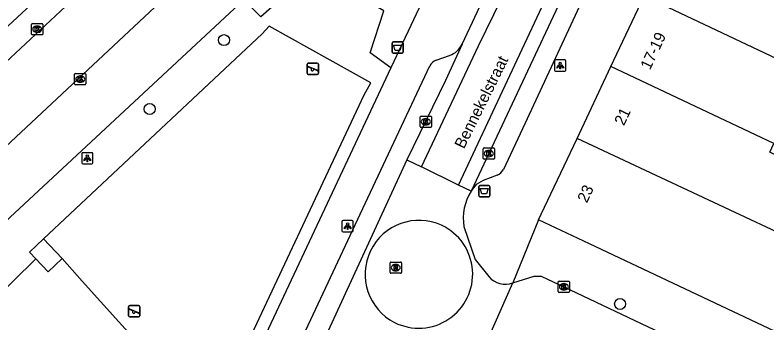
# Model space of a CAD drawing. Extents: x 159822 to 160765, y 380693 to 381634.
# Drawn here: x 160159 to 160225.7, y 381490.4 to 381517.7 of the extents above; entities that cross this region are included whole.
import ezdxf

# ---------------------------------------------------------------- set-up
doc = ezdxf.new("R2010")
doc.units = 0
for name, color, linetype in [('IMGEO_Afvalbak', 7, 'Continuous'), ('IMGEO_Boom', 7, 'Continuous'), ('IMGEO_Groenvoorziening', 7, 'Continuous'), ('IMGEO_Hek', 7, 'Continuous'), ('IMGEO_Kolk', 7, 'Continuous'), ('IMGEO_Lichtpunt', 7, 'Continuous'), ('IMGEO_Openbare_ruimte_label', 7, 'Continuous'), ('IMGEO_Pand', 7, 'Continuous'), ('IMGEO_Pand_nummerreeks', 7, 'Continuous'), ('IMGEO_Parkeervlak_open', 7, 'Continuous'), ('IMGEO_Rijbaan_lokaal_gesloten', 7, 'Continuous'), ('IMGEO_Rijbaan_lokaal_open', 7, 'Continuous'), ('IMGEO_Rioolput', 7, 'Continuous'), ('IMGEO_Speelvoorziening', 7, 'Continuous'), ('IMGEO_Voetpad_open', 7, 'Continuous')]:
    doc.layers.add(name, color=color, linetype=linetype)

msp = doc.modelspace()

# ---------------------------------------------------------------- linework, layer by layer
at = {"layer": 'IMGEO_Afvalbak'}
for p, q in [((160192.441, 381514.386), (160192.441, 381515.186)), ((160192.441, 381515.186), (160192.441, 381514.386)), ((160192.541, 381515.286), (160193.331, 381515.286)), ((160193.331, 381515.286), (160192.541, 381515.286)), ((160193.431, 381515.186), (160193.431, 381514.386)), ((160193.431, 381514.386), (160193.431, 381515.186)), ((160193.331, 381514.286), (160192.541, 381514.286)), ((160192.541, 381514.286), (160193.331, 381514.286)), ((160200.135, 381501.653), (160200.135, 381502.453)), ((160200.135, 381502.453), (160200.135, 381501.653)), ((160200.235, 381502.553), (160201.025, 381502.553)), ((160201.025, 381502.553), (160200.235, 381502.553)), ((160201.125, 381502.453), (160201.125, 381501.653)), ((160201.125, 381501.653), (160201.125, 381502.453)), ((160201.025, 381501.553), (160200.235, 381501.553)), ((160200.235, 381501.553), (160201.025, 381501.553))]:
    msp.add_line(p, q, dxfattribs=at)
for points in [[(160192.584, 381515), (160193.288, 381515), (160193.139, 381514.53), (160192.733, 381514.53), (160192.584, 381515)], [(160200.278, 381502.267), (160200.982, 381502.267), (160200.833, 381501.797), (160200.427, 381501.797), (160200.278, 381502.267)]]:
    msp.add_lwpolyline(points, dxfattribs=at)
for centre, start, end in [((160192.541, 381515.186), 90, 180), ((160192.541, 381515.186), 90, 180), ((160193.331, 381515.186), 0, 90), ((160193.331, 381515.186), 360, 90), ((160192.541, 381514.386), 180, 270), ((160192.541, 381514.386), 180, 270), ((160193.331, 381514.386), 270, 0), ((160193.331, 381514.386), 270, 0), ((160200.235, 381502.453), 90, 180), ((160200.235, 381502.453), 90, 180), ((160201.025, 381502.453), 0, 90), ((160201.025, 381502.453), 360, 90), ((160200.235, 381501.653), 180, 270), ((160200.235, 381501.653), 180, 270), ((160201.025, 381501.653), 270, 0), ((160201.025, 381501.653), 270, 0)]:
    msp.add_arc(centre, 0.1, start, end, dxfattribs=at)
at = {"layer": 'IMGEO_Boom'}
for centre in [(160177.513, 381515.444), (160170.915, 381509.333), (160212.692, 381492.04)]:
    msp.add_circle(centre, 0.489, dxfattribs=at)
at = {"layer": 'IMGEO_Groenvoorziening'}
for points in [[(160192.336, 381512.972), (160190.484, 381514.325), (160191.703, 381518.048), (160185.933, 381521.407), (160184.737, 381521.011), (160180.794, 381517.52), (160179.28, 381519.057)], [(160178.058, 381485.251), (160178.153, 381485.454), (160189.969, 381510.58), (160190.545, 381511.66), (160181.534, 381516.692), (160180.912, 381516.008), (160161.494, 381497.825)], [(160161.494, 381497.825), (160160.238, 381496.64), (160160.793, 381496.052)], [(160163.145, 381496.074), (160161.494, 381497.825)], [(160156.718, 381492.041), (160160.793, 381496.052)], [(160160.793, 381496.052), (160161.889, 381494.889), (160163.145, 381496.074)], [(160163.145, 381496.074), (160164.913, 381494.072), (160171.689, 381486.562)]]:
    msp.add_lwpolyline(points, dxfattribs=at)
at = {"layer": 'IMGEO_Hek'}
for points in [[(160190.545, 381511.66), (160181.534, 381516.692)], [(160161.494, 381497.825), (160180.912, 381516.008)], [(160178.058, 381485.251), (160178.153, 381485.454), (160189.969, 381510.58), (160190.545, 381511.66)], [(160164.913, 381494.072), (160171.689, 381486.562)]]:
    msp.add_lwpolyline(points, dxfattribs=at)
at = {"layer": 'IMGEO_Kolk'}
for p, q in [((160160.429, 381515.981), (160160.429, 381516.833)), ((160160.504, 381516.907), (160161.356, 381516.907)), ((160160.917, 381516.687), (160160.942, 381516.687)), ((160161.43, 381516.833), (160161.43, 381515.981)), ((160161.356, 381515.907), (160160.504, 381515.907)), ((160160.94, 381516.127), (160160.915, 381516.127)), ((160164.252, 381511.559), (160164.252, 381512.411)), ((160164.327, 381512.485), (160165.179, 381512.485)), ((160164.74, 381512.265), (160164.765, 381512.265)), ((160165.253, 381512.411), (160165.253, 381511.559)), ((160164.763, 381511.705), (160164.738, 381511.705)), ((160165.179, 381511.485), (160164.327, 381511.485)), ((160194.942, 381507.776), (160194.942, 381508.628)), ((160195.017, 381508.702), (160195.869, 381508.702)), ((160195.43, 381508.482), (160195.455, 381508.482)), ((160195.943, 381508.628), (160195.943, 381507.776)), ((160195.869, 381507.702), (160195.017, 381507.702)), ((160195.453, 381507.922), (160195.428, 381507.922)), ((160200.536, 381504.953), (160200.536, 381505.805)), ((160200.611, 381505.879), (160201.463, 381505.879)), ((160201.024, 381505.659), (160201.049, 381505.659)), ((160201.537, 381505.805), (160201.537, 381504.953)), ((160201.047, 381505.099), (160201.022, 381505.099)), ((160201.463, 381504.879), (160200.611, 381504.879)), ((160207.205, 381493.138), (160207.205, 381493.99)), ((160207.28, 381494.064), (160208.132, 381494.064)), ((160207.693, 381493.844), (160207.718, 381493.844)), ((160208.206, 381493.99), (160208.206, 381493.138)), ((160208.132, 381493.064), (160207.28, 381493.064)), ((160207.716, 381493.284), (160207.691, 381493.284))]:
    msp.add_line(p, q, dxfattribs=at)
for points in [[(160160.429, 381515.981), (160160.429, 381516.833)], [(160160.504, 381516.907), (160161.356, 381516.907)], [(160160.75, 381516.607), (160160.873, 381516.607), (160160.873, 381516.456), (160161.003, 381516.607), (160161.167, 381516.607), (160161.021, 381516.456), (160161.174, 381516.207), (160161.022, 381516.207), (160160.937, 381516.371), (160160.873, 381516.304), (160160.873, 381516.207), (160160.75, 381516.207), (160160.75, 381516.607)], [(160161.43, 381516.833), (160161.43, 381515.981)], [(160161.356, 381515.907), (160160.504, 381515.907)], [(160164.252, 381511.559), (160164.252, 381512.411)], [(160164.327, 381512.485), (160165.179, 381512.485)], [(160165.253, 381512.411), (160165.253, 381511.559)], [(160164.573, 381512.185), (160164.696, 381512.185), (160164.696, 381512.034), (160164.826, 381512.185), (160164.99, 381512.185), (160164.844, 381512.034), (160164.997, 381511.785), (160164.845, 381511.785), (160164.76, 381511.949), (160164.696, 381511.882), (160164.696, 381511.785), (160164.573, 381511.785), (160164.573, 381512.185)], [(160165.179, 381511.485), (160164.327, 381511.485)], [(160194.942, 381507.776), (160194.942, 381508.628)], [(160195.017, 381508.702), (160195.869, 381508.702)], [(160195.263, 381508.402), (160195.386, 381508.402), (160195.386, 381508.251), (160195.516, 381508.402), (160195.68, 381508.402), (160195.534, 381508.251), (160195.687, 381508.002), (160195.535, 381508.002), (160195.45, 381508.166), (160195.386, 381508.099), (160195.386, 381508.002), (160195.263, 381508.002), (160195.263, 381508.402)], [(160195.943, 381508.628), (160195.943, 381507.776)], [(160195.869, 381507.702), (160195.017, 381507.702)], [(160200.536, 381504.953), (160200.536, 381505.805)], [(160200.611, 381505.879), (160201.463, 381505.879)], [(160200.857, 381505.579), (160200.98, 381505.579), (160200.98, 381505.428), (160201.11, 381505.579), (160201.274, 381505.579), (160201.128, 381505.428), (160201.281, 381505.179), (160201.129, 381505.179), (160201.044, 381505.343), (160200.98, 381505.276), (160200.98, 381505.179), (160200.857, 381505.179), (160200.857, 381505.579)], [(160201.537, 381505.805), (160201.537, 381504.953)], [(160201.463, 381504.879), (160200.611, 381504.879)], [(160207.205, 381493.138), (160207.205, 381493.99)], [(160207.28, 381494.064), (160208.132, 381494.064)], [(160207.526, 381493.764), (160207.649, 381493.764), (160207.649, 381493.613), (160207.779, 381493.764), (160207.943, 381493.764), (160207.797, 381493.613), (160207.95, 381493.364), (160207.798, 381493.364), (160207.713, 381493.528), (160207.649, 381493.461), (160207.649, 381493.364), (160207.526, 381493.364), (160207.526, 381493.764)], [(160208.206, 381493.99), (160208.206, 381493.138)], [(160208.132, 381493.064), (160207.28, 381493.064)]]:
    msp.add_lwpolyline(points, dxfattribs=at)
for centre, start, end in [((160160.506, 381516.831), 91.55205, 178.44795), ((160160.506, 381516.831), 91.55205, 178.44795), ((160161.354, 381516.831), 1.55205, 88.44795), ((160161.354, 381516.831), 1.55205, 88.44795), ((160160.506, 381515.983), 181.55205, 268.44795), ((160160.506, 381515.983), 181.55205, 268.44795), ((160161.354, 381515.983), 271.55205, 358.44795), ((160161.354, 381515.983), 271.55205, 358.44795), ((160164.329, 381512.409), 91.55205, 178.44795), ((160164.329, 381512.409), 91.55205, 178.44795), ((160165.177, 381512.409), 1.55205, 88.44795), ((160165.177, 381512.409), 1.55205, 88.44795), ((160164.329, 381511.561), 181.55205, 268.44795), ((160164.329, 381511.561), 181.55205, 268.44795), ((160165.177, 381511.561), 271.55205, 358.44795), ((160165.177, 381511.561), 271.55205, 358.44795), ((160195.019, 381508.626), 91.55205, 178.44795), ((160195.019, 381508.626), 91.55205, 178.44795), ((160195.867, 381508.626), 1.55205, 88.44795), ((160195.867, 381508.626), 1.55205, 88.44795), ((160195.019, 381507.778), 181.55205, 268.44795), ((160195.019, 381507.778), 181.55205, 268.44795), ((160195.867, 381507.778), 271.55205, 358.44795), ((160195.867, 381507.778), 271.55205, 358.44795), ((160200.613, 381505.803), 91.55205, 178.44795), ((160200.613, 381505.803), 91.55205, 178.44795), ((160201.461, 381505.803), 1.55205, 88.44795), ((160201.461, 381505.803), 1.55205, 88.44795), ((160200.613, 381504.955), 181.55205, 268.44795), ((160200.613, 381504.955), 181.55205, 268.44795), ((160201.461, 381504.955), 271.55205, 358.44795), ((160201.461, 381504.955), 271.55205, 358.44795), ((160207.282, 381493.988), 91.55205, 178.44795), ((160207.282, 381493.988), 91.55205, 178.44795), ((160208.13, 381493.988), 1.55205, 88.44795), ((160208.13, 381493.988), 1.55205, 88.44795), ((160207.282, 381493.14), 181.55205, 268.44795), ((160207.282, 381493.14), 181.55205, 268.44795), ((160208.13, 381493.14), 271.55205, 358.44795), ((160208.13, 381493.14), 271.55205, 358.44795)]:
    msp.add_arc(centre, 0.0765, start, end, dxfattribs=at)
for centre, major_axis, ratio, start_param, end_param in [((160160.916, 381516.407), (-0.387, 0.002), 0.722429, 4.712389, 7.853982), ((160160.941, 381516.407), (-0.39, 0.002), 0.717154, 1.570796, 4.712389), ((160164.739, 381511.985), (-0.387, 0.002), 0.722429, 4.712389, 7.853982), ((160164.764, 381511.985), (-0.39, 0.002), 0.717154, 1.570796, 4.712389), ((160195.429, 381508.202), (-0.387, 0.002), 0.722429, 4.712389, 7.853982), ((160195.454, 381508.202), (-0.39, 0.002), 0.717154, 1.570796, 4.712389), ((160201.023, 381505.379), (-0.387, 0.002), 0.722429, 4.712389, 7.853982), ((160201.048, 381505.379), (-0.39, 0.002), 0.717154, 1.570796, 4.712389), ((160207.692, 381493.564), (-0.387, 0.002), 0.722429, 4.712389, 7.853982), ((160207.717, 381493.564), (-0.39, 0.002), 0.717154, 1.570796, 4.712389)]:
    msp.add_ellipse(centre, major_axis=major_axis, ratio=ratio, start_param=start_param, end_param=end_param, dxfattribs=at)
at = {"layer": 'IMGEO_Lichtpunt'}
for p, q in [((160206.874, 381513.588), (160206.874, 381512.781)), ((160206.874, 381513.588), (160206.874, 381512.781)), ((160207.776, 381513.683), (160206.968, 381513.683)), ((160207.776, 381513.683), (160206.968, 381513.683)), ((160207.87, 381512.781), (160207.87, 381513.588)), ((160207.87, 381512.781), (160207.87, 381513.588)), ((160206.968, 381512.687), (160207.776, 381512.687)), ((160206.968, 381512.687), (160207.776, 381512.687)), ((160164.882, 381505.363), (160164.882, 381504.556)), ((160164.882, 381505.363), (160164.882, 381504.556)), ((160165.784, 381505.458), (160164.976, 381505.458)), ((160165.784, 381505.458), (160164.976, 381505.458)), ((160165.878, 381504.556), (160165.878, 381505.363)), ((160165.878, 381504.556), (160165.878, 381505.363)), ((160164.976, 381504.462), (160165.784, 381504.462)), ((160164.976, 381504.462), (160165.784, 381504.462)), ((160187.995, 381499.338), (160187.995, 381498.531)), ((160187.995, 381499.338), (160187.995, 381498.531)), ((160188.897, 381499.433), (160188.089, 381499.433)), ((160188.897, 381499.433), (160188.089, 381499.433)), ((160188.991, 381498.531), (160188.991, 381499.338)), ((160188.991, 381498.531), (160188.991, 381499.338)), ((160188.089, 381498.437), (160188.897, 381498.437)), ((160188.089, 381498.437), (160188.897, 381498.437))]:
    msp.add_line(p, q, dxfattribs=at)
for points in [[(160207.248, 381513.252), (160207.287, 381513.224), (160207.099, 381512.962), (160207.061, 381512.989), (160207.248, 381513.252)], [(160207.35, 381513.204), (160207.397, 381513.204), (160207.397, 381512.882), (160207.35, 381512.882), (160207.35, 381513.204)], [(160207.46, 381513.224), (160207.498, 381513.251), (160207.685, 381512.989), (160207.646, 381512.961), (160207.46, 381513.224)], [(160165.256, 381505.027), (160165.295, 381504.999), (160165.107, 381504.737), (160165.069, 381504.764), (160165.256, 381505.027)], [(160165.358, 381504.979), (160165.405, 381504.979), (160165.405, 381504.657), (160165.358, 381504.657), (160165.358, 381504.979)], [(160165.468, 381504.999), (160165.506, 381505.026), (160165.693, 381504.764), (160165.654, 381504.736), (160165.468, 381504.999)], [(160188.369, 381499.002), (160188.408, 381498.974), (160188.22, 381498.712), (160188.182, 381498.739), (160188.369, 381499.002)], [(160188.471, 381498.954), (160188.518, 381498.954), (160188.518, 381498.632), (160188.471, 381498.632), (160188.471, 381498.954)], [(160188.581, 381498.974), (160188.619, 381499.001), (160188.806, 381498.739), (160188.767, 381498.711), (160188.581, 381498.974)]]:
    msp.add_lwpolyline(points, dxfattribs=at)
for centre in [(160207.373, 381513.386), (160165.381, 381505.161), (160188.494, 381499.136)]:
    msp.add_circle(centre, 0.0994, dxfattribs=at)
for centre, start, end in [((160206.968, 381513.588), 90, 180), ((160206.968, 381513.588), 90, 180), ((160207.776, 381513.588), 0, 90), ((160207.776, 381513.588), 0, 90), ((160206.968, 381512.781), 180, 270), ((160206.968, 381512.781), 180, 270), ((160207.776, 381512.781), 270, 0), ((160207.776, 381512.781), 270, 360), ((160164.976, 381505.363), 90, 180), ((160164.976, 381505.363), 90, 180), ((160165.784, 381505.363), 0, 90), ((160165.784, 381505.363), 0, 90), ((160164.976, 381504.556), 180, 270), ((160164.976, 381504.556), 180, 270), ((160165.784, 381504.556), 270, 0), ((160165.784, 381504.556), 270, 360), ((160188.089, 381499.338), 90, 180), ((160188.089, 381499.338), 90, 180), ((160188.897, 381499.338), 0, 90), ((160188.897, 381499.338), 0, 90), ((160188.089, 381498.531), 180, 270), ((160188.089, 381498.531), 180, 270), ((160188.897, 381498.531), 270, 0), ((160188.897, 381498.531), 270, 360)]:
    msp.add_arc(centre, 0.0946, start, end, dxfattribs=at)
at = {"layer": 'IMGEO_Pand'}
for points in [[(160211.878, 381513.097), (160214.836, 381519.361)], [(160236.261, 381509.241), (160214.836, 381519.361)], [(160208.868, 381506.722), (160211.878, 381513.097)], [(160232.932, 381502.141), (160225.986, 381505.502), (160226.344, 381506.259), (160211.878, 381513.097)], [(160205.457, 381499.498), (160205.694, 381500), (160208.868, 381506.722)], [(160230.368, 381496.674), (160208.868, 381506.722)], [(160226.962, 381489.344), (160209.966, 381497.369), (160205.457, 381499.498)]]:
    msp.add_lwpolyline(points, dxfattribs=at)
at = {"layer": 'IMGEO_Parkeervlak_open'}
msp.add_lwpolyline([(160153.811, 381495.399), (160179.28, 381519.057)], dxfattribs=at)
at = {"layer": 'IMGEO_Rijbaan_lokaal_gesloten'}
for points in [[(160195.057, 381504.19), (160200.114, 381514.925), (160204.894, 381524.689), (160207.351, 381531.14), (160213.112, 381546.814)], [(160198.355, 381502.582), (160207.047, 381521.179), (160210.249, 381527.541), (160213.934, 381533.948), (160219.567, 381543.105)], [(160198.669, 381515.096), (160203.444, 381525.268), (160203.524, 381525.464)], [(160209.036, 381522.424), (160199.46, 381502.043)], [(160198.669, 381515.096), (160197.176, 381511.876), (160193.743, 381504.831)]]:
    msp.add_lwpolyline(points, dxfattribs=at)
at = {"layer": 'IMGEO_Rijbaan_lokaal_open'}
for points in [[(160149.88, 381498.323), (160175.473, 381522.224), (160176.001, 381522.709)], [(160167.006, 381521.77), (160157.677, 381513.05), (160143.228, 381499.558)], [(160193.743, 381504.831), (160186.405, 381488.877)], [(160193.743, 381504.831), (160195.057, 381504.19)], [(160198.355, 381502.582), (160195.057, 381504.19)], [(160199.46, 381502.043), (160198.355, 381502.582)], [(160198.827, 381498.898), (160199.827, 381495.992), (160201.037, 381494.466)], [(160203.17, 381493.911), (160205.064, 381494.513), (160205.67, 381494.491), (160208.821, 381493.029), (160220.864, 381487.33), (160221.875, 381486.859), (160225.158, 381485.327), (160239.549, 381478.616), (160243.723, 381476.663)], [(160201.028, 381489.097), (160203.17, 381493.911)]]:
    msp.add_lwpolyline(points, dxfattribs=at)
for centre, radius, start, end in [((160203.24, 381499.646), 4.476, 147.61851, 189.62152), ((160194.839, 381494.665), 4.79, 65.27499, 243.08754), ((160194.812, 381494.678), 4.79, 243.45026, 64.91227), ((160202.49, 381495.672), 1.888, 219.70673, 291.12371)]:
    msp.add_arc(centre, radius, start, end, dxfattribs=at)
at = {"layer": 'IMGEO_Rioolput'}
for p, q in [((160192.267, 381494.832), (160192.267, 381495.684)), ((160192.342, 381495.758), (160193.194, 381495.758)), ((160193.268, 381495.684), (160193.268, 381494.832)), ((160192.778, 381494.978), (160192.753, 381494.978)), ((160192.755, 381495.538), (160192.78, 381495.538)), ((160193.194, 381494.758), (160192.342, 381494.758))]:
    msp.add_line(p, q, dxfattribs=at)
for points in [[(160192.267, 381494.832), (160192.267, 381495.684)], [(160192.342, 381495.758), (160193.194, 381495.758)], [(160193.268, 381495.684), (160193.268, 381494.832)], [(160192.856, 381495.456), (160192.604, 381495.458), (160192.604, 381495.058)], [(160192.604, 381495.058), (160192.728, 381495.058), (160192.728, 381495.22), (160192.739, 381495.22)], [(160192.782, 381495.377), (160192.728, 381495.377), (160192.728, 381495.296)], [(160192.728, 381495.296), (160192.78, 381495.296)], [(160192.786, 381495.191), (160192.857, 381495.058), (160192.997, 381495.058), (160192.932, 381495.184)], [(160193.194, 381494.758), (160192.342, 381494.758)]]:
    msp.add_lwpolyline(points, dxfattribs=at)
for centre, radius, start, end in [((160192.344, 381495.682), 0.0765, 91.55205, 178.44795), ((160192.344, 381495.682), 0.0765, 91.55205, 178.44795), ((160193.192, 381495.682), 0.0765, 1.55205, 88.44795), ((160193.192, 381495.682), 0.0765, 1.55205, 88.44795), ((160192.738, 381495.167), 0.0533, 26.02933, 88.69889), ((160192.764, 381495.485), 0.19, 274.7715, 282.96867), ((160192.788, 381495.281), 0.0964, 77.00612, 93.18647), ((160192.802, 381495.338), 0.0378, 276.66336, 79.67722), ((160192.855, 381495.346), 0.109, 350.36119, 89.41601), ((160192.853, 381495.346), 0.112, 277.58423, 350.98172), ((160192.837, 381495.131), 0.108, 29.51342, 73.79051), ((160192.344, 381494.834), 0.0765, 181.55205, 268.44795), ((160192.344, 381494.834), 0.0765, 181.55205, 268.44795), ((160193.192, 381494.834), 0.0765, 271.55205, 358.44795), ((160193.192, 381494.834), 0.0765, 271.55205, 358.44795)]:
    msp.add_arc(centre, radius, start, end, dxfattribs=at)
for centre, major_axis, ratio, start_param, end_param in [((160192.754, 381495.258), (-0.387, 0.002), 0.722429, 4.712389, 7.853982), ((160192.779, 381495.258), (-0.39, 0.002), 0.717154, 1.570796, 4.712389)]:
    msp.add_ellipse(centre, major_axis=major_axis, ratio=ratio, start_param=start_param, end_param=end_param, dxfattribs=at)
at = {"layer": 'IMGEO_Speelvoorziening'}
for p, q in [((160184.906, 381512.507), (160184.906, 381513.307)), ((160184.906, 381513.307), (160184.906, 381512.507)), ((160185.289, 381512.935), (160184.95, 381513.072)), ((160184.975, 381513.132), (160185.851, 381512.779)), ((160185.006, 381513.407), (160185.796, 381513.407)), ((160185.796, 381513.407), (160185.006, 381513.407)), ((160185.896, 381513.307), (160185.896, 381512.507)), ((160185.896, 381512.507), (160185.896, 381513.307)), ((160185.796, 381512.407), (160185.006, 381512.407)), ((160185.006, 381512.407), (160185.796, 381512.407)), ((160185.827, 381512.719), (160185.487, 381512.856)), ((160169.043, 381490.992), (160169.043, 381491.792)), ((160169.043, 381491.792), (160169.043, 381490.992)), ((160169.426, 381491.42), (160169.087, 381491.557)), ((160169.112, 381491.617), (160169.988, 381491.264)), ((160169.143, 381491.892), (160169.933, 381491.892)), ((160169.933, 381491.892), (160169.143, 381491.892)), ((160170.033, 381491.792), (160170.033, 381490.992)), ((160170.033, 381490.992), (160170.033, 381491.792)), ((160169.933, 381490.892), (160169.143, 381490.892)), ((160169.143, 381490.892), (160169.933, 381490.892)), ((160169.964, 381491.204), (160169.624, 381491.341))]:
    msp.add_line(p, q, dxfattribs=at)
for centre, radius, start, end in [((160185.006, 381513.307), 0.1, 90, 180), ((160185.006, 381513.307), 0.1, 90, 180), ((160184.963, 381513.102), 0.0327, 68.07798, 248.07798), ((160185.368, 381512.845), 0.12, 130.99278, 5.16318), ((160185.796, 381513.307), 0.1, 0, 90), ((160185.796, 381513.307), 0.1, 360, 90), ((160185.006, 381512.507), 0.1, 180, 270), ((160185.006, 381512.507), 0.1, 180, 270), ((160185.796, 381512.507), 0.1, 270, 0), ((160185.796, 381512.507), 0.1, 270, 0), ((160185.839, 381512.749), 0.0327, 248.07798, 68.07798), ((160169.143, 381491.792), 0.1, 90, 180), ((160169.143, 381491.792), 0.1, 90, 180), ((160169.1, 381491.587), 0.0327, 68.07798, 248.07798), ((160169.933, 381491.792), 0.1, 0, 90), ((160169.933, 381491.792), 0.1, 360, 90), ((160169.143, 381490.992), 0.1, 180, 270), ((160169.143, 381490.992), 0.1, 180, 270), ((160169.505, 381491.33), 0.12, 130.99278, 5.16318), ((160169.933, 381490.992), 0.1, 270, 0), ((160169.933, 381490.992), 0.1, 270, 0), ((160169.976, 381491.234), 0.0327, 248.07798, 68.07798)]:
    msp.add_arc(centre, radius, start, end, dxfattribs=at)
at = {"layer": 'IMGEO_Voetpad_open'}
for points in [[(160143.228, 381499.558), (160141.59, 381501.281), (160156.169, 381514.856), (160156.251, 381514.784), (160163.641, 381521.648), (160166.333, 381521.56)], [(160210.243, 381520.958), (160204.233, 381508.009), (160202.328, 381503.966)], [(160195.088, 381518.813), (160193.368, 381515.165), (160192.336, 381512.972)], [(160196.36, 381513.67), (160197.557, 381514.082)], [(160192.336, 381512.972), (160179.181, 381485.02)], [(160182.592, 381485.039), (160189.615, 381500), (160195.788, 381513.154)], [(160201.782, 381503.464), (160200.528, 381502.992), (160199.902, 381502.626)], [(160205.457, 381499.498), (160203.17, 381493.911)]]:
    msp.add_lwpolyline(points, dxfattribs=at)
for centre, radius, start, end in [((160196.873, 381515.948), 1.988, 290.11732, 334.60421), ((160196.908, 381512.487), 1.304, 114.86887, 149.23823), ((160201.301, 381504.535), 1.173, 294.17311, 331.01862), ((160203.303, 381499.589), 4.56, 138.23078, 147.43423)]:
    msp.add_arc(centre, radius, start, end, dxfattribs=at)

# ---------------------------------------------------------------- texts
at = {"layer": 'IMGEO_Openbare_ruimte_label'}
msp.add_text('Bennekelstraat', height=1, rotation=63.56313, dxfattribs=at).set_placement((160198.825, 381505.732))
at = {"layer": 'IMGEO_Pand_nummerreeks'}
for s, rotation, p in [('17-19', 64.84995, (160215.348, 381512.74)), ('21', 64.53311, (160213.03, 381507.79)), ('23', 64.81951, (160209.747, 381500.943))]:
    msp.add_text(s, height=1, rotation=rotation, dxfattribs=at).set_placement(p)

doc.saveas('drawing.dxf')
